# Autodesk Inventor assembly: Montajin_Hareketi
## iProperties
Created: 2004-11
Part Number: Montajin_Hareketi
Cost Center: 0 lbmass
Document SubType Name: Assembly
Designer: busseym
Manufacturer: Standard
Standards Organization: Custom
Description: SWING ARM, LCD FLAT PANEL
Stock Number: SA-LCD-17
Dept. ID: Product Design
Description #2: ---
Finish #1: ---
Finish #2: ---
Material ID: ---
Project Number: ---
Author: busseym
